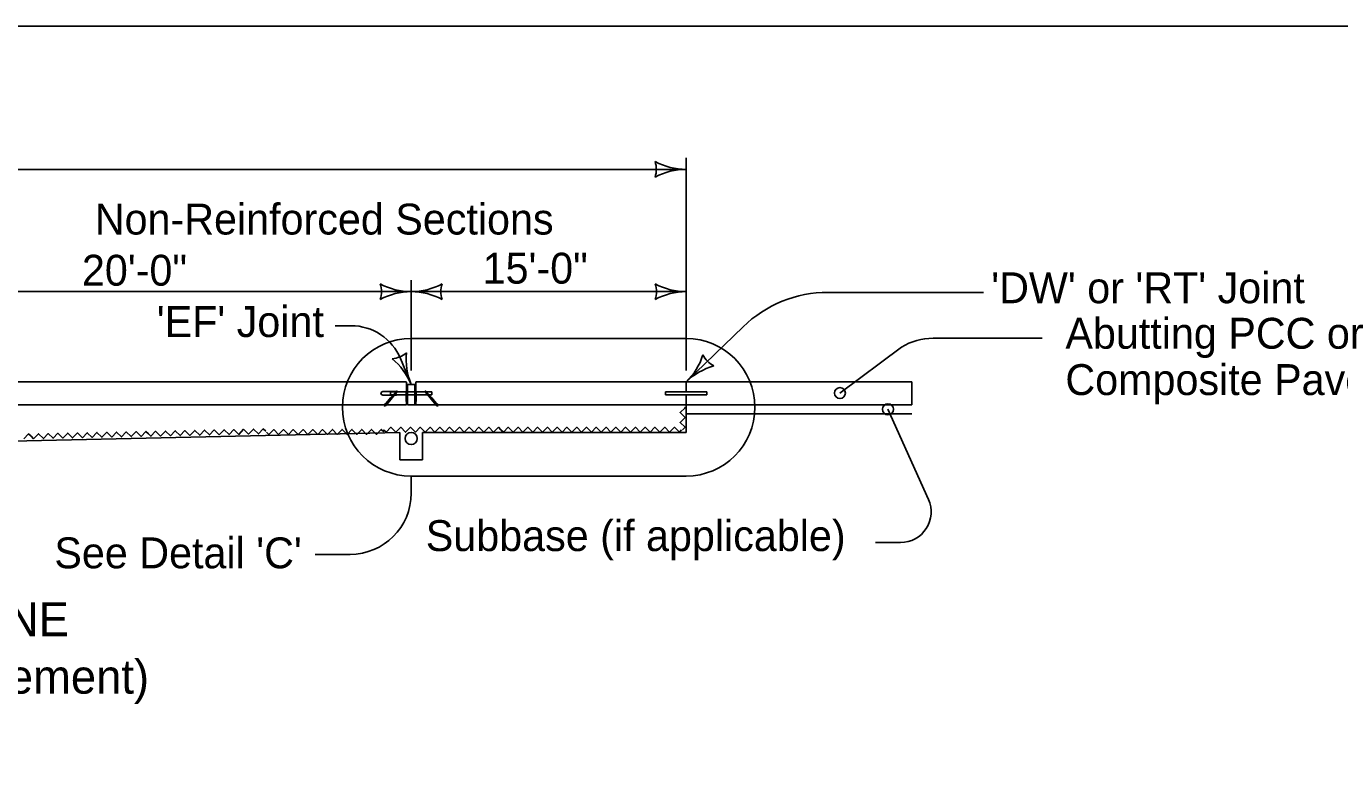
# Model space of a CAD drawing. Extents: x 8925 to 81668, y 4369 to 11918.
# Drawn here: x 14998 to 15849, y 9454 to 9944 of the extents above; entities that cross this region are included whole.
import ezdxf

# ---------------------------------------------------------------- set-up
doc = ezdxf.new("R2010")
doc.units = 0
for name, color, linetype in [('dsnShtPlotShapeBatchPrint', 7, 'Continuous'), ('dsnStdBorder', 7, 'Continuous'), ('Level 3', 7, 'Continuous'), ('Level 5', 7, 'Continuous'), ('SheetBorder', 7, 'Continuous')]:
    doc.layers.add(name, color=color, linetype=linetype)

msp = doc.modelspace()

# ---------------------------------------------------------------- linework, layer by layer
at = {"layer": 'dsnShtPlotShapeBatchPrint'}
for p, q in [((15425.93, 9721.18), (15425.93, 9858.81)), ((14086.46, 9851.38), (15425.93, 9851.38)), ((14891.33, 9772.18), (15247.73, 9772.18)), ((15247.73, 9721.18), (15247.73, 9779.61)), ((15247.73, 9772.18), (15425.93, 9772.18)), ((15517.89, 9771.72), (15618.58, 9771.72)), ((15198.46, 9750.14), (15208.81, 9750.14)), ((15425.93, 9713.75), (15462.83, 9749.44)), ((15247.73, 9741.85), (15425.93, 9741.85)), ((15586, 9742.01), (15656.61, 9742.01)), ((15565.43, 9736.25), (15525.58, 9706.49)), ((15582.96, 9637.69), (15556.72, 9695.99)), ((15247.73, 9652.75), (15247.73, 9641.65)), ((15247.73, 9652.75), (15425.93, 9652.75)), ((15548.68, 9609.76), (15564.91, 9609.76)), ((15185.49, 9602.05), (15208.13, 9602.05))]:
    msp.add_line(p, q, dxfattribs=at)
for centre, radius, start, end in [((15517.9, 9692.52), 79.2, 90, 134.04978), ((15208.81, 9715.5), 34.65, 22.59071, 90), ((15247.74, 9697.3), 44.55, 90, 270), ((15425.94, 9697.3), 44.55, 270, 90), ((15586, 9702.41), 39.6, 90, 121.29536), ((15208.14, 9641.65), 39.6, 270, 360), ((15564.91, 9629.56), 19.8, 270, 24.23803)]:
    msp.add_arc(centre, radius, start, end, dxfattribs=at)
at = {"layer": 'dsnStdBorder'}
for p, q in [((15240.8, 9728.81), (15247.73, 9712.15)), ((14089.43, 9713.75), (15244.34, 9713.75)), ((15244.35, 9713.75), (14891.33, 9713.75)), ((15244.76, 9707.24), (15244.76, 9713.34)), ((15244.76, 9703.41), (15244.76, 9713.33)), ((15244.76, 9712.15), (15245.36, 9712.15)), ((15244.82, 9712.15), (15244.82, 9703.41)), ((15244.88, 9712.15), (15244.88, 9703.41)), ((15244.94, 9712.15), (15244.94, 9703.41)), ((15245, 9712.15), (15245, 9703.41)), ((15245.06, 9712.15), (15245.06, 9703.41)), ((15245.12, 9712.15), (15245.12, 9703.41)), ((15245.18, 9712.15), (15245.18, 9703.41)), ((15245.24, 9712.15), (15245.24, 9703.41)), ((15245.29, 9712.15), (15245.29, 9703.41)), ((15250.11, 9712.15), (15245.36, 9712.15)), ((15245.36, 9712.15), (15245.36, 9707.22)), ((15250.11, 9707.22), (15250.11, 9712.15)), ((15250.11, 9712.15), (15250.7, 9712.15)), ((15250.17, 9712.15), (15250.17, 9703.41)), ((15250.23, 9712.15), (15250.23, 9703.41)), ((15250.28, 9712.15), (15250.28, 9703.41)), ((15250.35, 9712.15), (15250.35, 9703.41)), ((15250.4, 9712.15), (15250.4, 9703.41)), ((15250.47, 9712.15), (15250.47, 9703.41)), ((15250.52, 9712.15), (15250.52, 9703.41)), ((15250.59, 9712.15), (15250.59, 9703.41)), ((15250.64, 9712.15), (15250.64, 9703.41)), ((15250.7, 9713.34), (15250.7, 9707.22)), ((15250.7, 9703.41), (15250.7, 9713.33)), ((15425.93, 9713.75), (15251.12, 9713.75)), ((15251.12, 9713.75), (15425.93, 9713.75)), ((15425.93, 9707.25), (15425.93, 9713.75)), ((15425.93, 9713.75), (15425.93, 9707.25)), ((15425.93, 9713.75), (15572.12, 9713.75)), ((15572.12, 9713.75), (15572.12, 9698.9)), ((15229.32, 9707.51), (15237.88, 9707.51)), ((15229.32, 9705.14), (15235.89, 9705.14)), ((15234.44, 9703.41), (15232.69, 9701.32)), ((15235.37, 9703.41), (15233.62, 9701.32)), ((15234.37, 9705.43), (15234.37, 9707.22)), ((15234.37, 9707.22), (15237.64, 9707.22)), ((15234.37, 9705.43), (15236.14, 9705.43)), ((15238.13, 9707.8), (15234.44, 9703.41)), ((15235.37, 9703.41), (15238.67, 9707.34)), ((15236.82, 9705.14), (15238.23, 9705.14)), ((15237.07, 9705.43), (15244.41, 9705.43)), ((15238.23, 9705.43), (15238.23, 9705.14)), ((15238.56, 9707.22), (15244.41, 9707.22)), ((15244.41, 9701.28), (15244.41, 9707.22)), ((15244.41, 9701.28), (15244.41, 9707.22)), ((15244.58, 9707.39), (15244.58, 9707.39)), ((15244.76, 9701.32), (15244.76, 9703.41)), ((15244.82, 9703.41), (15244.82, 9701.32)), ((15244.88, 9703.41), (15244.88, 9701.32)), ((15244.94, 9703.41), (15244.94, 9701.32)), ((15245, 9703.41), (15245, 9701.32)), ((15245.06, 9703.41), (15245.06, 9701.32)), ((15245.12, 9703.41), (15245.12, 9701.32)), ((15245.18, 9703.41), (15245.18, 9701.32)), ((15245.24, 9703.41), (15245.24, 9701.32)), ((15245.29, 9703.41), (15245.29, 9701.32)), ((15245.36, 9707.22), (15245.36, 9705.43)), ((15245.36, 9707.22), (15250.11, 9707.22)), ((15245.36, 9705.43), (15250.11, 9705.43)), ((15245.36, 9705.43), (15245.36, 9703.41)), ((15245.36, 9703.41), (15245.36, 9701.32)), ((15250.11, 9707.22), (15250.11, 9705.43)), ((15250.11, 9705.43), (15250.11, 9703.41)), ((15250.11, 9703.41), (15250.11, 9701.32)), ((15250.17, 9703.41), (15250.17, 9701.32)), ((15250.23, 9703.41), (15250.23, 9701.32)), ((15250.28, 9703.41), (15250.28, 9701.32)), ((15250.35, 9703.41), (15250.35, 9701.32)), ((15250.4, 9703.41), (15250.4, 9701.32)), ((15250.47, 9703.41), (15250.47, 9701.32)), ((15250.52, 9703.41), (15250.52, 9701.32)), ((15250.59, 9703.41), (15250.59, 9701.32)), ((15250.64, 9703.41), (15250.64, 9701.32)), ((15250.7, 9701.32), (15250.7, 9703.41)), ((15251.06, 9707.22), (15251.06, 9701.28)), ((15251.06, 9701.28), (15251.06, 9707.22)), ((15251.06, 9707.22), (15256.9, 9707.22)), ((15251.06, 9705.43), (15258.39, 9705.43)), ((15260.09, 9703.41), (15256.8, 9707.34)), ((15257.34, 9707.8), (15261.02, 9703.41)), ((15257.83, 9707.22), (15261.1, 9707.22)), ((15259.33, 9705.43), (15261.1, 9705.43)), ((15260.09, 9703.41), (15261.84, 9701.32)), ((15261.02, 9703.41), (15262.77, 9701.32)), ((15261.1, 9705.43), (15261.1, 9707.22)), ((15412.56, 9705.4), (15412.56, 9707.25)), ((15412.56, 9707.25), (15425.93, 9707.25)), ((15425.93, 9705.4), (15412.56, 9705.4)), ((15412.57, 9705.39), (15412.57, 9707.25)), ((15412.57, 9707.25), (15439.3, 9707.25)), ((15439.3, 9705.39), (15412.57, 9705.39)), ((15425.93, 9698.9), (15425.93, 9705.4)), ((15425.93, 9705.39), (15425.93, 9698.9)), ((15439.3, 9707.25), (15439.3, 9705.39)), ((15230.66, 9698.9), (14089.43, 9698.9)), ((14891.33, 9698.9), (15230.66, 9698.9)), ((15232.69, 9701.32), (15230.28, 9698.45)), ((15230.83, 9697.99), (15230.28, 9698.45)), ((15230.66, 9698.9), (15244.76, 9698.9)), ((15244.76, 9698.9), (15230.66, 9698.9)), ((15233.62, 9701.32), (15230.83, 9697.99)), ((15244.76, 9698.9), (15244.76, 9701.32)), ((15244.76, 9698.9), (15244.76, 9701.28)), ((15244.82, 9701.32), (15244.82, 9698.9)), ((15244.88, 9701.32), (15244.88, 9698.9)), ((15244.94, 9701.32), (15244.94, 9698.9)), ((15245, 9701.32), (15245, 9698.9)), ((15245.06, 9701.32), (15245.06, 9698.9)), ((15245.12, 9701.32), (15245.12, 9698.9)), ((15245.18, 9701.32), (15245.18, 9698.9)), ((15245.24, 9701.32), (15245.24, 9698.9)), ((15245.29, 9701.32), (15245.29, 9698.9)), ((15245.36, 9701.32), (15245.36, 9698.9)), ((15245.36, 9698.9), (15250.11, 9698.9)), ((15250.11, 9701.32), (15250.11, 9698.9)), ((15250.11, 9698.9), (15425.93, 9698.9)), ((15250.17, 9701.32), (15250.17, 9698.9)), ((15250.23, 9701.32), (15250.23, 9698.9)), ((15250.28, 9701.32), (15250.28, 9698.9)), ((15250.35, 9701.32), (15250.35, 9698.9)), ((15250.4, 9701.32), (15250.4, 9698.9)), ((15250.47, 9701.32), (15250.47, 9698.9)), ((15250.52, 9701.32), (15250.52, 9698.9)), ((15250.59, 9701.32), (15250.59, 9698.9)), ((15250.64, 9701.32), (15250.64, 9698.9)), ((15250.7, 9698.9), (15250.7, 9701.32)), ((15250.7, 9701.28), (15250.7, 9698.9)), ((15250.7, 9698.9), (15425.93, 9698.9)), ((15261.84, 9701.32), (15264.64, 9697.99)), ((15262.77, 9701.32), (15265.19, 9698.45)), ((15264.64, 9697.99), (15265.19, 9698.45)), ((15425.93, 9698.9), (15425.93, 9681.08)), ((15425.93, 9698.9), (15572.12, 9698.9)), ((15572.12, 9692.96), (15425.93, 9692.96)), ((15240.31, 9681.08), (14123.07, 9655.84)), ((15240.31, 9681.08), (15240.31, 9663.26)), ((15255.16, 9681.08), (15425.93, 9681.08)), ((15255.16, 9681.08), (15255.16, 9663.26)), ((15240.31, 9663.26), (15255.16, 9663.26))]:
    msp.add_line(p, q, dxfattribs=at)
for points in [[(15250.7, 9707.22), (15250.7, 9707.22)], [(15423.62, 9682.79), (15425.21, 9684.38), (15422.04, 9687.54), (15425.2, 9690.71), (15422.03, 9693.88), (15425.2, 9697.05), (15424.77, 9697.48)], [(14996.7, 9676.81), (14999.8, 9680.05), (15001.41, 9678.5)], [(15001.41, 9678.5), (15003.03, 9676.95), (15006.13, 9680.18), (15009.37, 9677.08), (15012.47, 9680.32), (15015.7, 9677.22), (15018.8, 9680.45), (15022.04, 9677.35), (15025.14, 9680.59), (15028.37, 9677.49), (15031.47, 9680.72), (15034.71, 9677.63), (15037.81, 9680.86), (15041.04, 9677.76), (15044.14, 9680.99), (15047.37, 9677.9), (15050.47, 9681.13), (15053.71, 9678.03), (15056.81, 9681.27), (15060.05, 9678.17), (15063.14, 9681.4), (15066.38, 9678.3), (15069.48, 9681.54), (15072.71, 9678.44), (15075.81, 9681.67), (15077.43, 9680.12)], [(15077.43, 9680.12), (15079.05, 9678.57), (15082.15, 9681.81), (15085.38, 9678.71), (15088.48, 9681.94), (15091.72, 9678.85), (15094.81, 9682.08), (15098.05, 9678.98), (15101.15, 9682.21), (15104.39, 9679.12), (15107.49, 9682.35), (15110.72, 9679.25), (15113.82, 9682.49), (15117.05, 9679.39), (15120.16, 9682.62), (15123.39, 9679.52), (15126.49, 9682.76), (15129.73, 9679.66), (15132.82, 9682.89), (15136.06, 9679.79), (15139.16, 9683.03), (15142.39, 9679.93), (15145.5, 9683.16), (15148.73, 9680.07), (15151.83, 9683.3), (15153.45, 9681.75)], [(15153.9, 9681.28), (15155.49, 9679.7), (15158.65, 9682.87), (15161.82, 9679.71), (15164.99, 9682.88), (15168.16, 9679.72), (15171.32, 9682.89), (15174.49, 9679.73), (15177.66, 9682.9), (15180.83, 9679.73), (15183.99, 9682.91), (15187.17, 9679.74), (15190.33, 9682.91), (15193.5, 9679.75), (15196.67, 9682.92), (15199.84, 9679.76), (15203, 9682.93), (15206.17, 9679.77), (15209.34, 9682.94), (15212.51, 9679.77), (15215.67, 9682.95), (15218.85, 9679.78), (15222.01, 9682.96), (15225.18, 9679.79), (15228.35, 9682.97), (15229.93, 9681.38)], [(15229.87, 9682.78), (15231.46, 9681.19), (15234.63, 9684.36), (15237.79, 9681.19), (15240.96, 9684.36), (15244.13, 9681.19), (15247.3, 9684.36), (15250.47, 9681.2), (15253.63, 9684.37), (15256.8, 9681.2), (15259.97, 9684.37), (15263.14, 9681.2), (15266.31, 9684.37), (15269.47, 9681.21), (15272.64, 9684.37), (15275.81, 9681.21), (15278.98, 9684.37), (15282.15, 9681.21), (15285.31, 9684.38), (15288.48, 9681.21), (15291.65, 9684.38), (15294.82, 9681.21), (15297.99, 9684.38), (15301.15, 9681.21), (15304.32, 9684.38), (15305.91, 9682.8)], [(15305.91, 9682.8), (15307.49, 9681.22), (15310.66, 9684.39), (15313.83, 9681.22), (15316.99, 9684.39), (15320.16, 9681.22), (15323.33, 9684.39), (15326.5, 9681.23), (15329.67, 9684.39), (15332.83, 9681.23), (15336, 9684.4), (15339.17, 9681.23), (15342.34, 9684.4), (15345.51, 9681.23), (15348.67, 9684.4), (15351.84, 9681.24), (15355.01, 9684.41), (15358.18, 9681.24), (15361.35, 9684.41), (15364.51, 9681.24), (15367.68, 9684.41), (15370.85, 9681.25), (15374.02, 9684.41), (15377.19, 9681.25), (15380.35, 9684.41), (15381.94, 9682.83)], [(15381.94, 9682.83), (15383.52, 9681.25), (15386.69, 9684.42), (15389.86, 9681.25), (15393.03, 9684.42), (15396.19, 9681.25), (15399.36, 9684.42), (15402.53, 9681.25), (15405.7, 9684.42), (15408.87, 9681.26), (15412.03, 9684.43), (15415.2, 9681.26), (15418.37, 9684.43), (15421.54, 9681.26), (15422.91, 9682.63)]]:
    msp.add_lwpolyline(points, dxfattribs=at)
for centre, radius in [((15235.38, 9704.9), 0.238), ((15259.84, 9705.2), 0.238), ((15230.55, 9699.14), 0.238), ((15264.92, 9699.14), 0.238), ((15247.74, 9677.12), 3.96)]:
    msp.add_circle(centre, radius, dxfattribs=at)
for centre, radius, start, end in [((15390.09, 9851.38), 16.51, 342.26665, 17.73335), ((15425.93, 9894.13), 42.75, 241.92751, 270), ((15390.09, 9851.38), 16.51, 342.26665, 17.73335), ((15425.93, 9894.13), 42.75, 241.92751, 270), ((15425.93, 9808.63), 42.75, 90, 118.07249), ((15425.93, 9808.63), 42.75, 90, 118.07249), ((15244.35, 9713.34), 0.416, 360, 90), ((15244.35, 9713.34), 0.416, 0, 90), ((15251.12, 9713.34), 0.416, 90, 180), ((15251.12, 9713.34), 0.416, 90, 180), ((15229.32, 9706.33), 1.19, 90, 270), ((15238.4, 9707.57), 0.356, 320.00367, 139.99636), ((15244.59, 9707.22), 0.178, 5.43269, 180), ((15244.59, 9707.22), 0.178, 0, 180), ((15244.59, 9707.22), 0.178, 0, 180), ((15250.88, 9707.22), 0.178, 0, 180), ((15250.88, 9707.22), 0.178, 0, 180), ((15257.07, 9707.57), 0.356, 40.00364, 219.99633), ((15244.59, 9701.28), 0.178, 180, 359.93724), ((15244.59, 9701.28), 0.178, 180, 0), ((15250.88, 9701.28), 0.178, 180, 0), ((15250.88, 9701.28), 0.178, 180, 0)]:
    msp.add_arc(centre, radius, start, end, dxfattribs=at)
for points in [[(15251.06, 9707.1), (15251.09, 9707.09), (15251.12, 9707.1), (15251.15, 9707.1), (15251.17, 9707.1), (15251.19, 9707.09), (15251.2, 9707.1)], [(15251.06, 9706.98), (15251.09, 9706.97), (15251.12, 9706.98), (15251.15, 9706.98), (15251.17, 9706.98), (15251.19, 9706.97), (15251.2, 9706.98)], [(15251.06, 9706.86), (15251.09, 9706.86), (15251.12, 9706.86), (15251.15, 9706.86), (15251.17, 9706.86), (15251.19, 9706.86), (15251.2, 9706.86)], [(15251.06, 9706.74), (15251.09, 9706.74), (15251.12, 9706.74), (15251.15, 9706.74), (15251.17, 9706.74), (15251.19, 9706.74), (15251.2, 9706.74)], [(15251.06, 9706.62), (15251.09, 9706.62), (15251.12, 9706.62), (15251.15, 9706.62), (15251.17, 9706.62), (15251.19, 9706.62), (15251.2, 9706.62)], [(15251.06, 9706.5), (15251.09, 9706.5), (15251.12, 9706.5), (15251.15, 9706.5), (15251.17, 9706.5), (15251.19, 9706.5), (15251.2, 9706.5)], [(15251.06, 9706.38), (15251.09, 9706.38), (15251.12, 9706.38), (15251.15, 9706.38), (15251.17, 9706.38), (15251.19, 9706.38), (15251.2, 9706.38)], [(15251.06, 9706.27), (15251.09, 9706.26), (15251.12, 9706.27), (15251.15, 9706.27), (15251.17, 9706.27), (15251.19, 9706.26), (15251.2, 9706.27)], [(15251.06, 9706.15), (15251.09, 9706.14), (15251.12, 9706.15), (15251.15, 9706.15), (15251.17, 9706.15), (15251.19, 9706.14), (15251.2, 9706.15)], [(15251.06, 9706.03), (15251.09, 9706.02), (15251.12, 9706.03), (15251.15, 9706.03), (15251.17, 9706.03), (15251.19, 9706.02), (15251.2, 9706.03)], [(15251.06, 9705.91), (15251.09, 9705.91), (15251.12, 9705.91), (15251.15, 9705.91), (15251.17, 9705.91), (15251.19, 9705.91), (15251.2, 9705.91)], [(15251.06, 9705.79), (15251.09, 9705.79), (15251.12, 9705.79), (15251.15, 9705.79), (15251.17, 9705.79), (15251.19, 9705.79), (15251.2, 9705.79)], [(15251.06, 9705.67), (15251.09, 9705.67), (15251.12, 9705.67), (15251.15, 9705.67), (15251.17, 9705.67), (15251.19, 9705.67), (15251.2, 9705.67)], [(15251.06, 9705.55), (15251.09, 9705.55), (15251.12, 9705.55), (15251.15, 9705.55), (15251.17, 9705.55), (15251.19, 9705.55), (15251.2, 9705.55)]]:
    msp.add_spline(points, degree=3, dxfattribs=at)
at = {"layer": 'Level 3'}
for centre, radius, start, end in [((15212.1, 9772.18), 16.42, 342.26665, 17.73335), ((15247.73, 9814.68), 42.5, 241.92751, 270), ((15247.73, 9729.68), 42.5, 90, 118.07249), ((15247.73, 9814.68), 42.5, 270, 298.07249), ((15247.73, 9729.68), 42.5, 61.92751, 90), ((15283.37, 9772.18), 16.42, 162.26665, 197.73335), ((15390.3, 9772.18), 16.42, 342.26665, 17.73335), ((15425.93, 9814.68), 42.5, 241.92751, 270), ((15425.93, 9729.68), 42.5, 90, 118.07249), ((15234.04, 9745.05), 16.42, 274.86526, 310.33197), ((15286.97, 9728.48), 42.5, 174.52613, 202.59862), ((15396.38, 9744.3), 42.5, 314.0496, 342.12209), ((15451.55, 9738.53), 16.42, 206.31625, 241.78295), ((15208.5, 9695.82), 42.5, 22.59862, 50.6711), ((15455.48, 9683.2), 42.5, 105.97712, 134.0496)]:
    msp.add_arc(centre, radius, start, end, dxfattribs=at)
at = {"layer": 'Level 5'}
for centre in [(15525.58, 9706.49), (15556.72, 9695.99)]:
    msp.add_circle(centre, 3.54, dxfattribs=at)
at = {"layer": 'SheetBorder'}
msp.add_lwpolyline([(13732.52, 9944.02), (16867.53, 9944.02), (16867.53, 7924.02), (13732.52, 7924.02)], close=True, dxfattribs=at)

# ---------------------------------------------------------------- texts
at = {"layer": 'dsnShtPlotShapeBatchPrint'}
for s, height, p in [('Non-Reinforced Sections', 20, (15042.71, 9809.17)), ('15\'-0"', 20, (15294.05, 9777.38)), ('20\'-0"', 20, (15034.36, 9776.06)), ("'DW' or 'RT' Joint", 20, (15623.64, 9764.69)), ("'EF' Joint", 20, (15082.86, 9742.8)), ('Abutting PCC or', 20, (15671.68, 9735.23)), ('Composite Pavement', 20, (15671.68, 9705.23)), ('Subbase (if applicable)', 20, (15257.2, 9604.2)), ("See Detail 'C'", 20, (15016.51, 9593.04)), ('(Abutting PCC or Composite Pavement)', 22, (14556.32, 9511.86))]:
    msp.add_text(s, height=height, dxfattribs=at).set_placement(p)
at = {"layer": 'dsnStdBorder'}
msp.add_text('SECTION THRU CENTERLINE', height=22, dxfattribs=at).set_placement((14610.72, 9549.05))

doc.saveas('drawing.dxf')
